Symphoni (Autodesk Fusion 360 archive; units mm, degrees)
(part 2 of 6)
extrude "Extrude4" new body sketch "Sketch25" profile of L1 L2 L4 C1 C2 L5 L6 L7 L8 L9 L10 L11 L12 L13 L14 L15 L16 C4 C5 along normal blind 3
extrude "Extrude5" new body sketch "Sketch24" profile of L1 L7 L10 L11 L12 L13 L14 L16 along normal blind 12 and against normal blind 9
combine "Combine1"
fillet "Fillet1" radius 1
offset_faces "OffsetFaces1" distance -0.1
sketch "Sketch26" plane through (0, 0, 13.9004) normal (0, 0, 1) x axis (-1, 0, 0)
  line L1 (-214.3877, -143.2359) -> (-214.3877, -209.1659)
  line L2 (-222.3877, -143.2359) -> (-214.3877, -143.2359)
  line L3 (-222.3877, -209.1659) -> (-222.3877, -143.2359)
  line L4 (-214.3877, -209.1659) -> (-222.3877, -209.1659)
  line L5 (-222.3877, -176.2009) -> (-214.3877, -176.2009)
  circle C1 centre (-218.3877, -156.5062) radius 2.1
  circle C2 centre (-218.3877, -195.8956) radius 2.1
  point P8 (-214.3877, -176.2009)
  point P9 (-222.3877, -176.2009)
  midpoint L1 P8
  midpoint L3 P9
  symmetric C1 C2 L5
  dimension "d225" diameter C1 = 4.2
  dimension "d226" diameter C2 = 4.2
extrude "Extrude6" cut sketch "Sketch26" profile of C1 C2 against normal blind 12
sketch "acrylic'" plane through (0, 0, 88.7) normal (0, 0, 1) x axis (-1, 0, 0)
  line L1 (-313.7625, -161.3779) -> (-313.7625, -215.1735)
  line L2 (-206.1516, -161.3779) -> (-313.7625, -161.3779)
  line L3 (-206.1516, -186.4735) -> (-206.1516, -161.3779)
  line L4 (-206.1515, -186.4735) -> (-206.1516, -186.4735)
  line L5 (-206.1515, -188.1735) -> (-206.1515, -186.4735)
  line L6 (-206.1516, -188.1735) -> (-206.1515, -188.1735)
  line L7 (-206.1516, -213.4735) -> (-206.1516, -188.1735)
  line L8 (-206.1515, -213.4735) -> (-206.1516, -213.4735)
  line L9 (-206.1515, -215.1735) -> (-206.1515, -213.4735)
  line L10 (-313.7625, -215.1735) -> (-206.1515, -215.1735)
  line L11 (-313.7625, -125.5942) -> (-313.7625, -152.5942)
  line L12 (-206.1516, -125.5942) -> (-313.7625, -125.5942)
  line L13 (-206.1516, -152.5942) -> (-206.1516, -125.5942)
  line L14 (-313.7625, -152.5942) -> (-206.1516, -152.5942)
  line L15 (-209.081, -225) -> (-311.081, -225)
  line L16 (-199.081, -5) -> (-199.081, -215)
  line L17 (-311.081, 5) -> (-209.081, 5)
  line L18 (-321.081, -215) -> (-321.081, -5)
  line L19 (-313.7625, -188.1735) -> (-206.1516, -188.1735)
  line L20 (-206.1515, -215.1735) -> (-313.7625, -215.1735)
  line L21 (-206.1515, -213.4735) -> (-206.1515, -215.1735)
  line L22 (-206.1516, -213.4735) -> (-206.1515, -213.4735)
  line L23 (-206.1516, -188.1735) -> (-206.1516, -213.4735)
  line L24 (-206.1516, -152.5942) -> (-313.7625, -152.5942)
  line L25 (-313.7625, -161.3779) -> (-206.1516, -161.3779)
  line L26 (-313.7625, -152.5942) -> (-313.7625, -125.5942)
  line L27 (-313.7625, -215.1735) -> (-313.7625, -188.1735)
  line L28 (-313.7625, -186.4735) -> (-313.7625, -161.3779)
  line L29 (-206.1516, -161.3779) -> (-206.1516, -186.4735)
  line L30 (-206.1516, -125.5942) -> (-206.1516, -152.5942)
  line L31 (-311.081, -225) -> (-209.081, -225)
  line L32 (-206.1516, -186.4735) -> (-313.7625, -186.4735)
  line L33 (-321.081, -5) -> (-321.081, -215)
  line L34 (-209.081, 5) -> (-311.081, 5)
  line L35 (-199.081, -215) -> (-199.081, -5)
  line L36 (-313.7625, -125.5942) -> (-206.1516, -125.5942)
  arc A1 centre (-311.081, -215) radius 10 clockwise from (-311.081, -225) to (-321.081, -215)
  arc A2 centre (-209.081, -215) radius 10 clockwise from (-199.081, -215) to (-209.081, -225)
  arc A3 centre (-209.081, -5) radius 10 clockwise from (-209.081, 5) to (-199.081, -5)
  arc A4 centre (-311.081, -5) radius 10 clockwise from (-321.081, -5) to (-311.081, 5)
  arc A5 centre (-311.081, -215) radius 10 clockwise from (-311.081, -225) to (-321.081, -215)
  arc A6 centre (-311.081, -5) radius 10 clockwise from (-321.081, -5) to (-311.081, 5)
  arc A7 centre (-209.081, -5) radius 10 clockwise from (-209.081, 5) to (-199.081, -5)
  arc A8 centre (-209.081, -215) radius 10 clockwise from (-199.081, -215) to (-209.081, -225)
position "Position16"
copy_paste "CopyPaste1"
component_from_bodies "Body->Comp14"
as_built_joint "As-built2"
as_built_joint "As-built3"
position "Position17"
sketch "Sketch29" plane through (0, 0, 85) normal (0, 0, 1) x axis (-1, 0, 0)
  line L1 (-207.0809, -138.3115) -> (-215.3243, -138.3115)
  line L2 (-207.0809, -205.1908) -> (-207.0809, -138.3115)
  line L3 (-318.7625, -205.1908) -> (-207.0809, -205.1908)
  line L4 (-318.7625, -138.3115) -> (-318.7625, -205.1908)
  line L5 (-315.3243, -138.3115) -> (-318.7625, -138.3115)
  line L6 (-315.3243, -25.6421) -> (-315.3243, -138.3115)
  line L7 (-215.3243, -25.6421) -> (-315.3243, -25.6421)
  line L8 (-215.3243, -138.3115) -> (-215.3243, -25.6421)
  line L9 (-330.9988, 0) -> (-19.0012, 0)
  line L10 (-330.9988, -252) -> (-330.9988, 0)
  line L11 (-19.0012, -252) -> (-330.9988, -252)
  line L12 (-19.0012, 0) -> (-19.0012, -252)
  circle C1 centre (-107.2113, -126.4161) radius 53.6774
  circle C2 centre (-107.2113, -126.4161) radius 54.6774
  dimension "d246" = 1
extrude "Extrude7" cut sketch "Sketch29" profile of C1 C2 against normal blind 20
component_insert "Component Insert11"
work_plane "WorkPlane13" AlongDistance -18
extrude "Extrude7" new body sketch "Sketch19" profile of L1 A1 L2 A2 L3 A3 L4 A4 A9 L9 A10 L10 A11 L11 A12 L12 C1 A13 A14 A15 A16 A17 A18 A19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 along normal blind 2
sketch "Sketch28" plane through (0, -20, 0) normal (0, -1, 0) x axis (1, 0, 0)
  line L1 (345, 75) -> (345, 10)
  line L2 (10, 80) -> (340, 80)
  line L3 (5, 10) -> (5, 75)
  line L4 (340, 5) -> (10, 5)
  line L5 (340, 5) -> (10, 5)
  line L6 (5, 10) -> (5, 75)
  line L7 (10, 80) -> (340, 80)
  line L8 (345, 75) -> (345, 10)
  line L9 (350, 75) -> (350, 10)
  line L10 (340, 0) -> (10, 0)
  line L11 (0, 10) -> (0, 75)
  line L12 (10, 85) -> (340, 85)
  arc A1 centre (340, 75) radius 5 clockwise from (340, 80) to (345, 75)
  arc A2 centre (10, 75) radius 5 clockwise from (5, 75) to (10, 80)
  arc A3 centre (10, 10) radius 5 clockwise from (10, 5) to (5, 10)
  arc A4 centre (340, 10) radius 5 clockwise from (345, 10) to (340, 5)
  arc A5 centre (340, 10) radius 5 clockwise from (345, 10) to (340, 5)
  arc A6 centre (10, 10) radius 5 clockwise from (10, 5) to (5, 10)
  arc A7 centre (10, 75) radius 5 clockwise from (5, 75) to (10, 80)
  arc A8 centre (340, 75) radius 5 clockwise from (340, 80) to (345, 75)
  arc A9 centre (340, 75) radius 10 clockwise from (340, 85) to (350, 75)
  arc A10 centre (340, 10) radius 10 clockwise from (350, 10) to (340, 0)
  arc A11 centre (10, 10) radius 10 clockwise from (10, 0) to (0, 10)
  arc A12 centre (10, 75) radius 10 clockwise from (0, 75) to (10, 85)
component_insert "Component Insert10"
position "Position15"
extrude "Extrude8" cut sketch "Sketch16" profile of L7 L8 L9 L10 against normal blind 3
extrude "Extrude9" cut sketch "Sketch17" profile of C1 against normal blind 20
sketch "Sketch18" plane through (0, -16, 0) normal (0, -1, 0) x axis (1, 0, 0)
  circle C1 centre (72.9825, 42.5) radius 27.5
extrude "Extrude10" cut sketch "Sketch18" against normal blind 20
joint "Assemble2" alignAngle 0 alignOffsetX 0 alignOffsetY 0 alignOffsetZ 0
work_plane "WorkPlane1" AlongDistance -18
work_plane "WorkPlane2" AlongDistance -18
work_plane "WorkPlane3" AlongDistance -18
work_plane "WorkPlane4" AlongDistance -18
work_plane "WorkPlane5" AlongDistance -18
work_plane "WorkPlane6" AlongDistance -18
work_plane "WorkPlane7" AlongDistance -18
work_plane "WorkPlane8" AlongDistance -18
work_plane "WorkPlane9" AlongDistance -18
work_plane "WorkPlane10" AlongDistance -18
work_plane "WorkPlane11" AlongDistance -18
copy_paste_bodies "CopyPasteBodies1"
split "Split1"
as_built_joint "As-built1"
sketch "Sketch4" plane through (0, 0, 85) normal (0, 0, 1) x axis (-1, 0, 0)
  line L1 (-207.0809, -138.3115) -> (-215.3243, -138.3115)
  line L2 (-207.0809, -205.1908) -> (-207.0809, -138.3115)
  line L3 (-318.7625, -205.1908) -> (-207.0809, -205.1908)
  line L4 (-318.7625, -138.3115) -> (-318.7625, -205.1908)
  line L5 (-315.3243, -138.3115) -> (-318.7625, -138.3115)
  line L6 (-315.3243, -25.6421) -> (-315.3243, -138.3115)
  line L7 (-215.3243, -25.6421) -> (-315.3243, -25.6421)
  line L8 (-215.3243, -138.3115) -> (-215.3243, -25.6421)
  line L9 (-330.9988, 0) -> (-19.0012, 0)
  line L10 (-330.9988, -216) -> (-330.9988, 0)
  line L11 (-19.0012, -216) -> (-330.9988, -216)
  line L12 (-19.0012, 0) -> (-19.0012, -216)
component_from_bodies "Body->Comp2"
component_from_bodies "Body->Comp3"
component_from_bodies "Body->Comp4"
component_from_bodies "Body->Comp5"
component_from_bodies "Body->Comp6"
component_from_bodies "Body->Comp7"
component_from_bodies "Body->Comp8"
component_from_bodies "Body->Comp9"
component_from_bodies "Body->Comp10"
component_from_bodies "Body->Comp11"
component_from_bodies "Body->Comp12"
component_from_bodies "Body->Comp13"
sketch "Sketch5" plane through (0, 0, 0) normal (0, 0, 1) x axis (1, 0, 0)
  line L1 (-620, 0) -> (-400, 0)
  line L2 (-620, 530) -> (-620, 0)
  line L3 (-400, 1000) -> (-620, 1000)
  line L4 (-400, 0) -> (-400, 1000)
  line L5 (-1600, 1000) -> (-400, 1000)
  line L6 (-1600, 530) -> (-1600, 1000)
  line L7 (-620, 530) -> (-1600, 530)
  line L8 (-400, 1000) -> (-400, 530)
  point P2 (-400, 0)
  point P3 (-620, 0)
  point P5 (-400, 1000)
  point P6 (-1600, 1000)
  horizontal L1
  vertical L2
  horizontal L3
  vertical L4
  horizontal L5
  vertical L6
  horizontal L7
  vertical L8
  dimension "d89" distance P2 P3 = 220
  dimension "d90" distance P2 P5 = 1000
  dimension "d91" distance P5 P6 = 1200
  dimension "d92" distance L1 L7 = 530
step "Arrange1" sketch "Sketch5" AngleFromX 0 Priority 500 AngleFromX 0 Priority 500 AngleFromX 0 Priority 500 AngleFromX 0 Priority 500 AngleFromX 0 Priority 500 AngleFromX 0 Priority 500 AngleFromX 0 Priority 500 AngleFromX 0 Priority 500 AngleFromX 0 Priority 500 AngleFromX 0 Priority 500 AngleFromX 0 Priority 500 AngleFromX 0 Priority 500 originOffsetX 0 originOffsetY 0 grainDirection 0 objectSpacing 18 frameWidth 20 placementClearance 0
component_insert "Component Insert6"
position "Position6"
sketch "Sketch6" plane through (0, 0, 0) normal (0, 0, 1) x axis (1, 0, 0)
  line L1 (-681.6057, 956.4633) -> (-681.6057, 944.4633)
  line L2 (-674.6057, 956.4633) -> (-681.6057, 956.4633)
  line L3 (-674.6057, 965.4645) -> (-674.6057, 956.4633)
  line L4 (-749.6057, 975.4645) -> (-684.6057, 975.4645)
  line L5 (-759.6057, 635.4645) -> (-759.6057, 965.4645)
  line L6 (-684.6057, 625.4645) -> (-749.6057, 625.4645)
  line L7 (-674.6057, 644.4657) -> (-674.6057, 635.4645)
  line L8 (-681.6057, 644.4657) -> (-674.6057, 644.4657)
  line L9 (-681.6057, 656.4657) -> (-681.6057, 644.4657)
  line L10 (-686.6057, 656.4657) -> (-681.6057, 656.4657)
  line L11 (-686.6057, 639.6645) -> (-686.6057, 656.4657)
  line L12 (-742.6057, 637.4645) -> (-688.8057, 637.4645)
  line L13 (-747.6057, 958.4645) -> (-747.6057, 642.4645)
  line L14 (-688.6057, 963.4645) -> (-742.6057, 963.4645)
  line L15 (-686.6057, 944.4633) -> (-686.6057, 961.4645)
  line L16 (-681.6057, 944.4633) -> (-686.6057, 944.4633)
  line L17 (-789.6057, 593.4633) -> (-789.6057, 909.4633)
  line L18 (-848.6057, 588.4633) -> (-794.6057, 588.4633)
  line L19 (-850.6057, 607.4645) -> (-850.6057, 590.4633)
  line L20 (-855.6057, 607.4645) -> (-850.6057, 607.4645)
  line L21 (-855.6057, 595.4645) -> (-855.6057, 607.4645)
  line L22 (-862.6057, 595.4645) -> (-855.6057, 595.4645)
  line L23 (-862.6057, 586.4633) -> (-862.6057, 595.4645)
  line L24 (-787.6057, 576.4633) -> (-852.6057, 576.4633)
  line L25 (-777.6057, 916.4633) -> (-777.6057, 586.4633)
  line L26 (-852.6057, 926.4633) -> (-787.6057, 926.4633)
  line L27 (-862.6057, 907.4621) -> (-862.6057, 916.4633)
  line L28 (-855.6057, 907.4621) -> (-862.6057, 907.4621)
  line L29 (-855.6057, 895.4621) -> (-855.6057, 907.4621)
  line L30 (-850.6057, 895.4621) -> (-855.6057, 895.4621)
  line L31 (-850.6057, 912.2633) -> (-850.6057, 895.4621)
  line L32 (-794.6057, 914.4633) -> (-848.4057, 914.4633)
  line L33 (-816.07, 944.4633) -> (-821.07, 944.4633)
  line L34 (-816.07, 956.4633) -> (-816.07, 944.4633)
  line L35 (-809.07, 956.4633) -> (-816.07, 956.4633)
  line L36 (-809.07, 965.4645) -> (-809.07, 956.4633)
  line L37 (-884.07, 975.4645) -> (-819.07, 975.4645)
  line L38 (-894.07, 635.4645) -> (-894.07, 965.4645)
  line L39 (-819.07, 625.4645) -> (-884.07, 625.4645)
  line L40 (-809.07, 644.4657) -> (-809.07, 635.4645)
  line L41 (-816.07, 644.4657) -> (-809.07, 644.4657)
  line L42 (-816.07, 656.4657) -> (-816.07, 644.4657)
  line L43 (-821.07, 656.4657) -> (-816.07, 656.4657)
  line L44 (-821.07, 639.6645) -> (-821.07, 656.4657)
  line L45 (-877.07, 637.4645) -> (-823.27, 637.4645)
  line L46 (-882.07, 958.4645) -> (-882.07, 642.4645)
  line L47 (-823.07, 963.4645) -> (-877.07, 963.4645)
  line L48 (-821.07, 944.4633) -> (-821.07, 961.4645)
  line L49 (-987.07, 926.4633) -> (-922.07, 926.4633)
  line L50 (-997.07, 907.4621) -> (-997.07, 916.4633)
  line L51 (-990.07, 907.4621) -> (-997.07, 907.4621)
  line L52 (-990.07, 895.4621) -> (-990.07, 907.4621)
  line L53 (-985.07, 895.4621) -> (-990.07, 895.4621)
  line L54 (-985.07, 912.2633) -> (-985.07, 895.4621)
  line L55 (-929.07, 914.4633) -> (-982.87, 914.4633)
  line L56 (-924.07, 593.4633) -> (-924.07, 909.4633)
  line L57 (-983.07, 588.4633) -> (-929.07, 588.4633)
  line L58 (-985.07, 607.4645) -> (-985.07, 590.4633)
  line L59 (-990.07, 607.4645) -> (-985.07, 607.4645)
  line L60 (-990.07, 595.4645) -> (-990.07, 607.4645)
  line L61 (-997.07, 595.4645) -> (-990.07, 595.4645)
  line L62 (-997.07, 586.4633) -> (-997.07, 595.4645)
  line L63 (-922.07, 576.4633) -> (-987.07, 576.4633)
  line L64 (-912.07, 916.4633) -> (-912.07, 586.4633)
  line L65 (-957.5344, 963.4645) -> (-1011.5344, 963.4645)
  line L66 (-955.5344, 944.4633) -> (-955.5344, 961.4645)
  line L67 (-950.5344, 944.4633) -> (-955.5344, 944.4633)
  line L68 (-950.5344, 956.4633) -> (-950.5344, 944.4633)
  line L69 (-943.5344, 956.4633) -> (-950.5344, 956.4633)
  line L70 (-943.5344, 965.4645) -> (-943.5344, 956.4633)
  line L71 (-1018.5344, 975.4645) -> (-953.5344, 975.4645)
  line L72 (-1028.5344, 635.4645) -> (-1028.5344, 965.4645)
  line L73 (-953.5344, 625.4645) -> (-1018.5344, 625.4645)
  line L74 (-943.5344, 644.4657) -> (-943.5344, 635.4645)
  line L75 (-950.5344, 644.4657) -> (-943.5344, 644.4657)
  line L76 (-950.5344, 656.4657) -> (-950.5344, 644.4657)
  line L77 (-955.5344, 656.4657) -> (-950.5344, 656.4657)
  line L78 (-955.5344, 639.6645) -> (-955.5344, 656.4657)
  line L79 (-1011.5344, 637.4645) -> (-957.7344, 637.4645)
  line L80 (-1016.5344, 958.4645) -> (-1016.5344, 642.4645)
  line L81 (-1089.9988, 944.4633) -> (-1089.9988, 961.4645)
  line L82 (-1084.9988, 944.4633) -> (-1089.9988, 944.4633)
  line L83 (-1084.9988, 956.4633) -> (-1084.9988, 944.4633)
  line L84 (-1077.9988, 956.4633) -> (-1084.9988, 956.4633)
  line L85 (-1077.9988, 965.4645) -> (-1077.9988, 956.4633)
  line L86 (-1152.9988, 975.4645) -> (-1087.9988, 975.4645)
  line L87 (-1162.9988, 635.4645) -> (-1162.9988, 965.4645)
  line L88 (-1087.9988, 625.4645) -> (-1152.9988, 625.4645)
  line L89 (-1077.9988, 644.4657) -> (-1077.9988, 635.4645)
  line L90 (-1084.9988, 644.4657) -> (-1077.9988, 644.4657)
  line L91 (-1084.9988, 656.4657) -> (-1084.9988, 644.4657)
  line L92 (-1089.9988, 656.4657) -> (-1084.9988, 656.4657)
  line L93 (-1089.9988, 639.6645) -> (-1089.9988, 656.4657)
  line L94 (-1145.9988, 637.4645) -> (-1092.1988, 637.4645)
  line L95 (-1150.9988, 958.4645) -> (-1150.9988, 642.4645)
  line L96 (-1091.9988, 963.4645) -> (-1145.9988, 963.4645)
  line L97 (-1563, 871) -> (-1247, 871)
  line L98 (-1568, 930) -> (-1568, 876)
  line L99 (-1548.9988, 932) -> (-1566, 932)
  line L100 (-1548.9988, 937) -> (-1548.9988, 932)
  line L101 (-1560.9988, 937) -> (-1548.9988, 937)
  line L102 (-1560.9988, 944) -> (-1560.9988, 937)
  line L103 (-1570, 944) -> (-1560.9988, 944)
  line L104 (-1580, 869) -> (-1580, 934)
  line L105 (-1240, 859) -> (-1570, 859)
  line L106 (-1230, 934) -> (-1230, 869)
  line L107 (-1249.0012, 944) -> (-1240, 944)
  line L108 (-1249.0012, 937) -> (-1249.0012, 944)
  line L109 (-1261.0012, 937) -> (-1249.0012, 937)
  line L110 (-1261.0012, 932) -> (-1261.0012, 937)
  line L111 (-1244.2, 932) -> (-1261.0012, 932)
  line L112 (-1242, 876) -> (-1242, 929.8)
  line L113 (-1516.7988, 902.4645) -> (-1499.9976, 902.4645)
  line L114 (-1518.9988, 958.4645) -> (-1518.9988, 904.6645)
  line L115 (-1197.9988, 963.4645) -> (-1513.9988, 963.4645)
  line L116 (-1192.9988, 904.4645) -> (-1192.9988, 958.4645)
  line L117 (-1212, 902.4645) -> (-1194.9988, 902.4645)
  line L118 (-1212, 897.4645) -> (-1212, 902.4645)
  line L119 (-1200, 897.4645) -> (-1212, 897.4645)
  line L120 (-1200, 890.4645) -> (-1200, 897.4645)
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position "Position7"
sketch "Sketch7" plane through (0, 228, 0) normal (0, 1, 0) x axis (-1, 0, 0)
  line L1 (-132.5, 60) -> (-217.5, 60)
  line L2 (-127.5, 30) -> (-127.5, 55)
  line L3 (-217.5, 25) -> (-132.5, 25)
  line L4 (-222.5, 55) -> (-222.5, 30)
  line L5 (-340, 85) -> (-10, 85)
  line L6 (-350, 10) -> (-350, 75)
  line L7 (-10, 0) -> (-340, 0)
  line L8 (0, 75) -> (0, 10)
  line L9 (0, 42.5) -> (-350, 42.5)
  line L10 (-175, 0) -> (-175, 85)
  circle C1 centre (-175, 6.9916) radius 2
  circle C2 centre (-340, 6.9916) radius 2
  circle C3 centre (-9.989, 78) radius 2
  circle C4 centre (-175, 79) radius 2
  circle C5 centre (-340, 78) radius 2
  circle C6 centre (-10, 7.35) radius 2
  arc A1 centre (-217.5, 55) radius 5 clockwise from (-222.5, 55) to (-217.5, 60)
  arc A2 centre (-132.5, 55) radius 5 clockwise from (-132.5, 60) to (-127.5, 55)
  arc A3 centre (-132.5, 30) radius 5 clockwise from (-127.5, 30) to (-132.5, 25)
  arc A4 centre (-217.5, 30) radius 5 clockwise from (-217.5, 25) to (-222.5, 30)
  arc A5 centre (-340, 75) radius 10 clockwise from (-350, 75) to (-340, 85)
  arc A6 centre (-340, 10) radius 10 clockwise from (-340, 0) to (-350, 10)
  arc A7 centre (-10, 10) radius 10 clockwise from (0, 10) to (-10, 0)
  arc A8 centre (-10, 75) radius 10 clockwise from (-10, 85) to (0, 75)
  point P32 (-350, 42.5)
  point P33 (0, 42.5)
  point P34 (-175, 85)
  point P35 (-175, 0)
  point P36 (-175, 42.5)
  midpoint L6 P32
  midpoint L8 P33
  midpoint L5 P34
  midpoint L7 P35
  midpoint L9 P36
position "Position8"
sketch "Sketch8" plane through (0, 228, 0) normal (0, 1, 0) x axis (-1, 0, 0)
  line L1 (-132.5, 60) -> (-217.5, 60)
  line L2 (-127.5, 30) -> (-127.5, 55)
  line L3 (-217.5, 25) -> (-132.5, 25)
  line L4 (-222.5, 55) -> (-222.5, 30)
  line L5 (-340, 85) -> (-10, 85)
  line L6 (-350, 10) -> (-350, 75)
  line L7 (-10, 0) -> (-340, 0)
  line L8 (0, 75) -> (0, 10)
  line L9 (-340, 85) -> (-10, 85)
  line L10 (-350, 10) -> (-350, 75)
  line L11 (-10, 0) -> (-340, 0)
  line L12 (0, 75) -> (0, 10)
  line L13 (-132.5, 60) -> (-217.5, 60)
  line L14 (-127.5, 30) -> (-127.5, 55)
  line L15 (-217.5, 25) -> (-132.5, 25)
  line L16 (-222.5, 55) -> (-222.5, 30)
  circle C1 centre (-175, 6.9916) radius 2
  circle C2 centre (-340, 6.9916) radius 2
  circle C3 centre (-9.989, 78) radius 2
  circle C4 centre (-175, 79) radius 2
  circle C5 centre (-340, 78) radius 2
  circle C6 centre (-10, 7.35) radius 2
  arc A1 centre (-217.5, 55) radius 5 clockwise from (-222.5, 55) to (-217.5, 60)
  arc A2 centre (-132.5, 55) radius 5 clockwise from (-132.5, 60) to (-127.5, 55)
  arc A3 centre (-132.5, 30) radius 5 clockwise from (-127.5, 30) to (-132.5, 25)
  arc A4 centre (-217.5, 30) radius 5 clockwise from (-217.5, 25) to (-222.5, 30)
  arc A5 centre (-340, 75) radius 10 clockwise from (-350, 75) to (-340, 85)
  arc A6 centre (-340, 10) radius 10 clockwise from (-340, 0) to (-350, 10)
  arc A7 centre (-10, 10) radius 10 clockwise from (0, 10) to (-10, 0)
  arc A8 centre (-10, 75) radius 10 clockwise from (-10, 85) to (0, 75)
  arc A9 centre (-340, 75) radius 10 clockwise from (-350, 75) to (-340, 85)
  arc A10 centre (-340, 10) radius 10 clockwise from (-340, 0) to (-350, 10)
  arc A11 centre (-10, 10) radius 10 clockwise from (0, 10) to (-10, 0)
  arc A12 centre (-10, 75) radius 10 clockwise from (-10, 85) to (0, 75)
  arc A13 centre (-132.5, 55) radius 5 clockwise from (-132.5, 60) to (-127.5, 55)
  arc A14 centre (-132.5, 30) radius 5 clockwise from (-127.5, 30) to (-132.5, 25)
  arc A15 centre (-217.5, 30) radius 5 clockwise from (-217.5, 25) to (-222.5, 30)
  arc A16 centre (-217.5, 55) radius 5 clockwise from (-222.5, 55) to (-217.5, 60)
sketch "Sketch9" plane through (0, 0, 0) normal (0, 1, 0) x axis (1, 0, 0)
  line L1 (-50, 0) -> (-50, -250)
  line L2 (436.214, 0) -> (-50, 0)
  line L3 (510, 0) -> (-50, 0)
  line L4 (510, -250) -> (510, 0)
  line L5 (-50, -250) -> (280, -250)
  line L6 (-50, 0) -> (-50, -250)
  line L7 (280, 0) -> (510, 0)
  line L8 (280, -390) -> (280, -250)
  line L9 (510, 0) -> (510, -390)
  line L10 (510, -547.191) -> (280, -390)
  line L11 (510, -390) -> (510, -547.191)
  point P2 (-50, 0)
  point P4 (510, 0)
  point P6 (-50, -250)
  point P7 (280, 0)
  point P9 (510, -390)
  vertical L1
  horizontal L2
  horizontal L3
  vertical L4
  horizontal L5
  vertical L6
  horizontal L7
  vertical L8
  vertical L9
  vertical L11
  dimension "d124" distance P2 P4 = 560
  dimension "d125" distance P2 P6 = 250
  dimension "d126" distance P4 P7 = 230
  dimension "d127" distance P4 P9 = 390
step "Arrange2" sketch "Sketch9" AngleFromX 0 Priority 500 AngleFromX 0 Priority 500 AngleFromX 0 Priority 500 originOffsetX 0 originOffsetY 0 grainDirection 0 objectSpacing 18 frameWidth 20 placementClearance 0
sketch "Sketch10" plane through (0, 0, 0) normal (0, 1, 0) x axis (1, 0, 0)
  line L1 (-20, -230) -> (310, -230)
  line L2 (310, -145) -> (-20, -145)
  line L3 (-30, -155) -> (-30, -220)
  line L4 (320, -220) -> (320, -155)
  line L5 (192.5, -175) -> (192.5, -200)
  line L6 (187.5, -205) -> (102.5, -205)
  line L7 (97.5, -200) -> (97.5, -175)
  line L8 (102.5, -170) -> (187.5, -170)
  line L9 (310, -127) -> (-20, -127)
  line L10 (-30, -117) -> (-30, -52)
  line L11 (-20, -42) -> (-10.9988, -42)
  line L12 (-10.9988, -42) -> (-10.9988, -49)
  line L13 (-10.9988, -49) -> (1.0012, -49)
  line L14 (1.0012, -49) -> (1.0012, -54)
  line L15 (1.0012, -54) -> (-15.8, -54)
  line L16 (-18, -56.2) -> (-18, -110)
  line L17 (-13, -115) -> (303, -115)
  line L18 (308, -110) -> (308, -56)
  line L19 (306, -54) -> (288.9988, -54)
  line L20 (288.9988, -54) -> (288.9988, -49)
  line L21 (288.9988, -49) -> (300.9988, -49)
  line L22 (300.9988, -49) -> (300.9988, -42)
  line L23 (300.9988, -42) -> (310, -42)
  line L24 (320, -52) -> (320, -117)
  line L25 (413, -392) -> (348, -392)
  line L26 (423, -372.9988) -> (423, -382)
  line L27 (416, -372.9988) -> (423, -372.9988)
  line L28 (416, -360.9988) -> (416, -372.9988)
  line L29 (411, -360.9988) -> (416, -360.9988)
  line L30 (411, -378) -> (411, -360.9988)
  line L31 (355, -380) -> (409, -380)
  line L32 (350, -59) -> (350, -375)
  line L33 (408.8, -54) -> (355, -54)
  line L34 (411, -73.0012) -> (411, -56.2)
  line L35 (416, -73.0012) -> (411, -73.0012)
  line L36 (416, -61.0012) -> (416, -73.0012)
  line L37 (423, -61.0012) -> (416, -61.0012)
  line L38 (423, -52) -> (423, -61.0012)
  line L39 (348, -42) -> (413, -42)
  line L40 (338, -382) -> (338, -52)
  arc A1 centre (-20, -155) radius 10 clockwise from (-30, -155) to (-20, -145)
  arc A2 centre (-20, -220) radius 10 clockwise from (-20, -230) to (-30, -220)
  arc A3 centre (310, -155) radius 10 clockwise from (310, -145) to (320, -155)
  arc A4 centre (310, -220) radius 10 clockwise from (320, -220) to (310, -230)
  arc A5 centre (102.5, -175) radius 5 clockwise from (97.5, -175) to (102.5, -170)
  arc A6 centre (102.5, -200) radius 5 clockwise from (102.5, -205) to (97.5, -200)
  arc A7 centre (187.5, -175) radius 5 clockwise from (187.5, -170) to (192.5, -175)
  arc A8 centre (187.5, -200) radius 5 clockwise from (192.5, -200) to (187.5, -205)
  arc A9 centre (-20, -117) radius 10 clockwise from (-20, -127) to (-30, -117)
  arc A10 centre (-20, -52) radius 10 clockwise from (-30, -52) to (-20, -42)
  arc A11 centre (-15.8, -56.2) radius 2.2 clockwise from (-18, -56.2) to (-15.8, -54)
  arc A12 centre (-13, -110) radius 5 clockwise from (-13, -115) to (-18, -110)
  arc A13 centre (303, -110) radius 5 clockwise from (308, -110) to (303, -115)
  arc A14 centre (306, -56) radius 2 clockwise from (306, -54) to (308, -56)
  arc A15 centre (310, -52) radius 10 clockwise from (310, -42) to (320, -52)
  arc A16 centre (310, -117) radius 10 clockwise from (320, -117) to (310, -127)
  arc A17 centre (348, -382) radius 10 clockwise from (348, -392) to (338, -382)
  arc A18 centre (413, -382) radius 10 clockwise from (423, -382) to (413, -392)
  arc A19 centre (409, -378) radius 2 clockwise from (411, -378) to (409, -380)
  arc A20 centre (355, -375) radius 5 clockwise from (355, -380) to (350, -375)
  arc A21 centre (355, -59) radius 5 clockwise from (350, -59) to (355, -54)
  arc A22 centre (408.8, -56.2) radius 2.2 clockwise from (408.8, -54) to (411, -56.2)
  arc A23 centre (413, -52) radius 10 clockwise from (413, -42) to (423, -52)
  arc A24 centre (348, -52) radius 10 clockwise from (338, -52) to (348, -42)
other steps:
base_feature "Base Feature1"
base_feature "Base Feature1" sketch "Sketch2"
extrude "Extrude1" cut sketch "Sketch2" profile of C1 C2 C3 C4 C5 C6 against normal blind 5 and along normal blind 15
base_feature "Base Feature1" bodies "Front"
extrude "Extrude3" cut sketch "Sketch3" profile of L5 L6 L7 L8 against normal blind 25
extrude "Extrude4" cut sketch "Sketch2" profile of C1 C2 C3 C4 C5 C6 against normal blind 5 and along normal blind 15
offset_faces "OffsetFaces1" distance 36
extrude "Extrude14" cut sketch "Sketch17" profile of L15 L16 L17 L22 against normal blind 6.5
create_component "CreateComponent1"
create_component "CreateComponent1"
create_component "CreateComponent2"
create_component "CreateComponent4" sketch "Sketch2"
place_component sketch "Sketch2"
remove_body "RemoveBody1"
base_feature "Base Feature1"
create_component "CreateComponent5"
base_feature "Base Feature1"
remove_body "RemoveBody2"
create_component "CreateComponent6"
base_feature "Base Feature1"
remove_body "RemoveBody3"
create_component "CreateComponent7"
base_feature "Base Feature1"
remove_body "RemoveBody4"
create_component "CreateComponent8"
base_feature "Base Feature1"
remove_body "RemoveBody5"
create_component "CreateComponent9"
base_feature "Base Feature1"
remove_body "RemoveBody6"
create_component "CreateComponent10"
base_feature "Base Feature1"
remove_body "RemoveBody7"
create_component "CreateComponent11"
base_feature "Base Feature1"
remove_body "RemoveBody8"
create_component "CreateComponent12"
base_feature "Base Feature1"
remove_body "RemoveBody9"
create_component "CreateComponent13"
base_feature "Base Feature1"
remove_body "RemoveBody10"
create_component "CreateComponent14"
base_feature "Base Feature1"
remove_body "RemoveBody11"
create_component "CreateComponent15"
base_feature "Base Feature1"
remove_body "RemoveBody12"
create_component "CreateComponent16"
base_feature "Base Feature1"
remove_body "RemoveBody13"
create_component "CreateComponent17"
create_component "CreateComponent1"
create_component "CreateComponent18"
create_component "CreateComponent1"
create_component "CreateComponent19" sketch "Sketch13"
joint_origin "JointOrigin1"
create_component "CreateComponent2"
remove_body "RemoveBody1"
joint_origin "JointOrigin10"
create_component "CreateComponent20"
create_component "CreateComponent21"
remove_body "RemoveBody14"
named bodies: "Front"

design "PCM5102_Modul_ksu_detail"
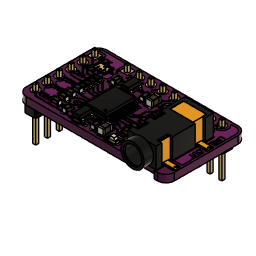
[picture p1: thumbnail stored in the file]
description: FreeCAD Model
part number: PCM5102_Modul
description: Part Number
part number: C13_C_0603_1608Metric_fe494fe29558
part number: U3_SOT_23_5_215b9efe0f9c
part number: U2_TSSOP_20_44x65mm_P065mm_d0068de2549f
part number: R7_R_0603_1608Metric_fcd2d6c932f5
part number: C2_C_0805_2012Metric_0ac201e7e1f9
part number: J3_PJ-327A_7183a15533ae
part number: D1_LED_0603_1608Metric_b5c2f6ca02fa
part number: Top_e102
part number: J2_PinHeader_1x09_P254mm_Vertical_94b9bb8abd76
base_feature "Base Feature1"
base_feature "Base Feature1"
base_feature "Base Feature1"
base_feature "Base Feature1"
base_feature "Base Feature1"
base_feature "Base Feature1"
base_feature "Base Feature1"
base_feature "Base Feature1"
base_feature "Base Feature1"
base_feature "Base Feature1"
base_feature "Base Feature1"
base_feature "Base Feature1"
base_feature "Base Feature1"
base_feature "Base Feature1"
base_feature "Base Feature1"
base_feature "Base Feature1"
base_feature "Base Feature1"
base_feature "Base Feature1"
sketch "Sketch1" plane through (0, 0, 0) normal (0, 0, 1) x axis (1, 0, 0)
  line L1 (1.8, -17.3) -> (23.58, -17.3)
  line L2 (0, -1.8) -> (0, -15.5)
  line L3 (23.58, -17.3) -> (23.93, -16.3)
  line L4 (23.93, -16.3) -> (28.93, -16.3)
  line L5 (28.93, -16.3) -> (29.28, -17.3)
  line L6 (29.28, -17.3) -> (30, -17.3)
  line L7 (31.8, -15.5) -> (31.8, -1.8)
  line L8 (30, 0) -> (1.8, 0)
  circle C1 centre (28.22, -1.7) radius 0.4999
  circle C2 centre (25.68, -1.7) radius 0.4999
  circle C3 centre (23.14, -1.7) radius 0.5
  circle C4 centre (20.6, -1.7) radius 0.5
  circle C5 centre (18.06, -1.7) radius 0.5
  circle C6 centre (15.52, -1.7) radius 0.4999
  circle C7 centre (12.98, -1.7) radius 0.5
  circle C8 centre (7.9, -1.7) radius 0.5
  circle C9 centre (1.55, -2.335) radius 0.5
  circle C10 centre (1.55, -4.875) radius 0.4999
  circle C11 centre (1.55, -7.415) radius 0.5
  circle C12 centre (1.55, -9.955) radius 0.5
  circle C13 centre (1.55, -12.495) radius 0.5
  circle C14 centre (1.55, -15.035) radius 0.5
  arc A1 centre (1.8, -15.5) radius 1.8 clockwise from (1.8, -17.3) to (0, -15.5)
  arc A2 centre (30, -15.5) radius 1.8 clockwise from (31.8, -15.5) to (30, -17.3)
  arc A3 centre (30, -1.8) radius 1.8 clockwise from (30, 0) to (31.8, -1.8)
  arc A4 centre (1.8, -1.8) radius 1.8 clockwise from (0, -1.8) to (1.8, 0)
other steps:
create_component "CreateComponent1"
create_component "CreateComponent1"
create_component "CreateComponent1"
create_component "CreateComponent2"
create_component "CreateComponent3"
create_component "CreateComponent4"
create_component "CreateComponent5"
create_component "CreateComponent6"
create_component "CreateComponent7"
create_component "CreateComponent2"
create_component "CreateComponent1"
create_component "CreateComponent2"
create_component "CreateComponent2"
create_component "CreateComponent1"
create_component "CreateComponent2"
create_component "CreateComponent3"
create_component "CreateComponent4"
create_component "CreateComponent5"
create_component "CreateComponent6"
create_component "CreateComponent7"
create_component "CreateComponent8"
create_component "CreateComponent9"

design "N20 DC MOTOR"
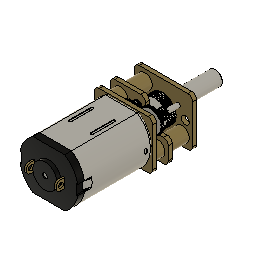
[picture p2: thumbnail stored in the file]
description: STEP AP214
part number: N20 DC MOTOR
base_feature "Base Feature"

design "New_Playback"
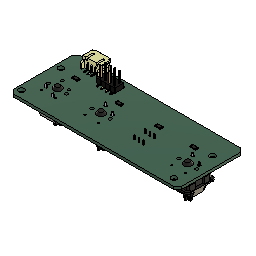
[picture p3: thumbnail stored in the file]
description: KiCad electronic assembly
part number: Playback_Controls 1
description: Part Number
part number: Ceramic
part number: Contacts
part number: Contacts (Mirror #1)
part number: Overcoat
part number: Resistor-1206
part number: PinHeader_2x04_P2.54mm_Vertical_SMD
part number: S3B-PH-SM4-TB--3DModel-STEP-269445
part number: MX1A-11NN
part number: SW_Btn_XLX
base_feature "Base Feature1"
base_feature "Base Feature1"
base_feature "Base Feature1"
base_feature "Base Feature1"
base_feature "Base Feature1"
base_feature "Base Feature1"
base_feature "Base Feature1"
base_feature "Base Feature1"
base_feature "Base Feature1"
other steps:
create_component "CreateComponent1"
create_component "CreateComponent1"
create_component "CreateComponent2"
create_component "CreateComponent3"
create_component "CreateComponent4"
create_component "CreateComponent2"
create_component "CreateComponent3"
create_component "CreateComponent4"
create_component "CreateComponent5"
create_component "CreateComponent6"

design "Laser Panel" references "LCD Display Mount", "Playback_Controls", "New_Playback", "XH-M577", "Playback_Controls_larger"
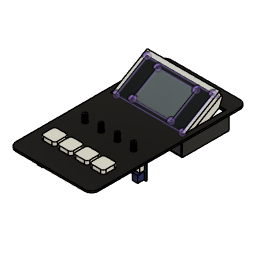
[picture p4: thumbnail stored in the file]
part number: Cherry MX Keycap
component_insert "Component Insert1"
position "Position1"
component_insert "Component Insert2"
component_insert "Component Insert3"
sketch "Sketch2" plane through (0, 0, 16.7) normal (0, 0, 1) x axis (-1, 0, 0)
  line L1 (36.7, 1.8) -> (36.7, 2.4)
  line L2 (38.05, 1.8) -> (36.7, 1.8)
  line L3 (38.05, 4.5) -> (38.05, 1.8)
  line L4 (40.45, 5.7) -> (39.1552, 5.7)
  line L5 (40.45, 12.8) -> (40.45, 5.7)
  line L6 (33.35, 12.8) -> (40.45, 12.8)
  line L7 (33.35, 11.5) -> (33.35, 12.8)
  line L8 (30.95, 10.2) -> (32.0499, 10.2)
  line L9 (30.95, 1.8) -> (30.95, 10.2)
  line L10 (34.7, 1.8) -> (30.95, 1.8)
  line L11 (34.7, 2.4) -> (34.7, 1.8)
  line L12 (36.7, 2.4) -> (34.7, 2.4)
  curve K1 (37.544, 5.3651) -> (37.1495, 11.1005)
  curve K2 (34.2541, 11.0973) -> (33.9191, 5.3212)
  line L13 (48.35, 0) -> (-48.35, 0)
  line L14 (48.35, 1.6) -> (48.35, 0)
  line L15 (-48.35, 1.6) -> (48.35, 1.6)
  line L16 (-48.35, 0) -> (-48.35, 1.6)
  line L17 (50, 97.6631) -> (-50, 97.6631)
  line L18 (50, -97.6631) -> (50, 97.6631)
  line L19 (-50, -97.6631) -> (50, -97.6631)
  line L20 (-50, 97.6631) -> (-50, -97.6631)
  line L21 (50, -97.6631) -> (-50, 97.6631)
  line L22 (-50, -97.6631) -> (50, 97.6631)
  line L23 (55, 115) -> (-55, 115)
  line L24 (55, -115) -> (55, 115)
  line L25 (-55, -115) -> (55, -115)
  line L26 (-55, 115) -> (-55, -115)
  line L27 (55, -115) -> (-55, 115)
  line L28 (-55, -115) -> (55, 115)
  line L29 (12.7, 1.8) -> (12.7, 2.4)
  line L30 (14.05, 1.8) -> (12.7, 1.8)
  line L31 (14.05, 4.5) -> (14.05, 1.8)
  line L32 (16.45, 5.7) -> (15.1552, 5.7)
  line L33 (16.45, 12.8) -> (16.45, 5.7)
  line L34 (9.35, 12.8) -> (16.45, 12.8)
  line L35 (9.35, 11.5) -> (9.35, 12.8)
  line L36 (6.95, 10.2) -> (8.0499, 10.2)
  line L37 (6.95, 1.8) -> (6.95, 10.2)
  line L38 (10.7, 1.8) -> (6.95, 1.8)
  line L39 (10.7, 2.4) -> (10.7, 1.8)
  line L40 (12.7, 2.4) -> (10.7, 2.4)
  curve K3 (13.544, 5.3651) -> (13.1495, 11.1005)
  curve K4 (10.2541, 11.0973) -> (9.9191, 5.3212)
  line L41 (-11.3, 1.8) -> (-11.3, 2.4)
  line L42 (-9.95, 1.8) -> (-11.3, 1.8)
  line L43 (-9.95, 4.5) -> (-9.95, 1.8)
  line L44 (-7.55, 5.7) -> (-8.8448, 5.7)
  line L45 (-7.55, 12.8) -> (-7.55, 5.7)
  line L46 (-14.65, 12.8) -> (-7.55, 12.8)
  line L47 (-14.65, 11.5) -> (-14.65, 12.8)
  line L48 (-17.05, 10.2) -> (-15.9501, 10.2)
  line L49 (-17.05, 1.8) -> (-17.05, 10.2)
  line L50 (-13.3, 1.8) -> (-17.05, 1.8)
  line L51 (-13.3, 2.4) -> (-13.3, 1.8)
  line L52 (-11.3, 2.4) -> (-13.3, 2.4)
  curve K5 (-10.456, 5.3651) -> (-10.8505, 11.1005)
  curve K6 (-13.7459, 11.0973) -> (-14.0809, 5.3212)
  line L53 (-35.3, 1.8) -> (-35.3, 2.4)
  line L54 (-33.95, 1.8) -> (-35.3, 1.8)
  line L55 (-33.95, 4.5) -> (-33.95, 1.8)
  line L56 (-31.55, 5.7) -> (-32.8448, 5.7)
  line L57 (-31.55, 12.8) -> (-31.55, 5.7)
  line L58 (-38.65, 12.8) -> (-31.55, 12.8)
  line L59 (-38.65, 11.5) -> (-38.65, 12.8)
  line L60 (-41.05, 10.2) -> (-39.9501, 10.2)
  line L61 (-41.05, 1.8) -> (-41.05, 10.2)
  line L62 (-37.3, 1.8) -> (-41.05, 1.8)
  line L63 (-37.3, 2.4) -> (-37.3, 1.8)
  line L64 (-35.3, 2.4) -> (-37.3, 2.4)
  curve K7 (-34.456, 5.3651) -> (-34.8505, 11.1005)
  curve K8 (-37.7459, 11.0973) -> (-38.0809, 5.3212)
  arc A1 centre (39.2541, 4.5) radius 1.2041 clockwise from (38.05, 4.5) to (39.1552, 5.7)
  arc A2 centre (32.0499, 11.5001) radius 1.3001 clockwise from (33.35, 11.5) to (32.0499, 10.2)
  arc A3 centre (35.7, 7.95) radius 3.4635 clockwise from (34.2541, 11.0973) to (37.1467, 11.0969)
  arc A4 centre (35.7, 7.95) radius 3.1752 clockwise from (37.544, 5.3651) to (33.9191, 5.3212)
  arc A5 centre (15.2541, 4.5) radius 1.2041 clockwise from (14.05, 4.5) to (15.1552, 5.7)
  arc A6 centre (8.0499, 11.5001) radius 1.3001 clockwise from (9.35, 11.5) to (8.0499, 10.2)
  arc A7 centre (11.7, 7.95) radius 3.4635 clockwise from (10.2541, 11.0973) to (13.1467, 11.0969)
  arc A8 centre (11.7, 7.95) radius 3.1752 clockwise from (13.544, 5.3651) to (9.9191, 5.3212)
  arc A9 centre (-8.7459, 4.5) radius 1.2041 clockwise from (-9.95, 4.5) to (-8.8448, 5.7)
  arc A10 centre (-15.9501, 11.5001) radius 1.3001 clockwise from (-14.65, 11.5) to (-15.9501, 10.2)
  arc A11 centre (-12.3, 7.95) radius 3.4635 clockwise from (-13.7459, 11.0973) to (-10.8533, 11.0969)
  arc A12 centre (-12.3, 7.95) radius 3.1753 clockwise from (-10.456, 5.3651) to (-14.0809, 5.3212)
  arc A13 centre (-32.7459, 4.5) radius 1.2041 clockwise from (-33.95, 4.5) to (-32.8448, 5.7)
  arc A14 centre (-39.9501, 11.5001) radius 1.3001 clockwise from (-38.65, 11.5) to (-39.9501, 10.2)
  arc A15 centre (-36.3, 7.95) radius 3.4635 clockwise from (-37.7459, 11.0973) to (-34.8533, 11.0969)
  arc A16 centre (-36.3, 7.95) radius 3.1752 clockwise from (-34.456, 5.3651) to (-38.0809, 5.3212)
  circle C1 centre (35.7, 7.95) radius 3.4635
  circle C2 centre (11.7, 7.95) radius 3.4679
  circle C3 centre (-12.3, 7.95) radius 3.4635
  circle C4 centre (-36.3, 7.95) radius 3.4635
  point P32 (0, 0)
  point P1 (0, 0)
  point P37 (0, 0)
  point P19 (34.2541, 11.0973)
  point P57 (13.1495, 11.1005)
  point P76 (-10.8533, 11.0969)
  point P98 (-34.8533, 11.0969)
  point P30 (50, -97.6631)
  point P31 (-50, -97.6631)
  point P35 (55, -115)
  point P36 (-55, -115)
  point P33 (-55, 115)
  horizontal L17
  perpendicular L17 L18
  parallel L17 L19
  parallel L18 L20
  coincident L21 P32
  coincident L22 P32
  coincident P1 P32
  horizontal L23
  perpendicular L23 L24
  parallel L23 L25
  parallel L24 L26
  coincident L27 P37
  coincident L28 P37
  coincident P32 P37
  concentric A3 C1
  coincident P19 C1
  concentric A7 C2
  coincident P57 C2
  concentric A11 C3
  coincident P76 C3
  concentric A15 C4
  coincident P98 C4
  dimension "d1" distance P30 P31 = 100
  dimension "d2" distance P35 P36 = 110
  dimension "d19" distance P33 P36 = 230
extrude "Extrude1" new body sketch "Sketch2" profile of L1 L2 L3 A1 L4 L5 L6 L7 A2 L8 L9 L10 L11 L12 A3 L13 L14 L15 L16 L17 L18 L19 L20 L23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 along normal blind 2
sketch "Sketch3" plane through (0, 0, 16.7) normal (0, 0, -1) x axis (1, 0, 0)
  line L1 (55, -115) -> (-55, -115)
  line L2 (55, 115) -> (55, -115)
  line L3 (-55, 115) -> (55, 115)
  line L4 (-55, -115) -> (-55, 115)
  circle C1 centre (-35.7, 7.95) radius 3.4635
  circle C2 centre (36.3, 7.95) radius 3.4635
  circle C3 centre (-11.7, 7.95) radius 3.4679
  circle C4 centre (12.3, 7.95) radius 3.4635
  circle C5 centre (39.33, 65.6) radius 1.55
  circle C6 centre (39.33, 37.5) radius 1.55
  circle C7 centre (-44.88, 37.5) radius 1.55
  circle C8 centre (-44.88, 65.6) radius 1.55
sketch "Sketch4" plane through (0, 0, 9.185) normal (0, 0, 1) x axis (-1, 0, 0)
  line L1 (30.1, 50.257) -> (29.1, 50.257)
  line L2 (30.1, 45.363) -> (30.1, 50.257)
  line L3 (29.1, 45.363) -> (30.1, 45.363)
  line L4 (29.1, 42.21) -> (29.1, 45.363)
  line L5 (28.703, 42.213) -> (29.1, 42.21)
  line L6 (27.953, 42.213) -> (28.703, 42.213)
  line L7 (27.953, 41.763) -> (27.953, 42.213)
  line L8 (33.253, 40.063) -> (29.653, 40.063)
  line L9 (33.253, 42.21) -> (33.253, 40.063)
  line L10 (38.147, 42.21) -> (33.253, 42.21)
  line L11 (38.147, 40.063) -> (38.147, 42.21)
  line L12 (41.747, 40.063) -> (38.147, 40.063)
  line L13 (43.447, 42.213) -> (43.447, 41.763)
  line L14 (42.697, 42.213) -> (43.447, 42.213)
  line L15 (42.3, 42.21) -> (42.697, 42.213)
  line L16 (42.3, 45.363) -> (42.3, 42.21)
  line L17 (41.3, 45.363) -> (42.3, 45.363)
  line L18 (41.3, 50.257) -> (41.3, 45.363)
  line L19 (42.3, 50.257) -> (41.3, 50.257)
  line L20 (42.3, 53.41) -> (42.3, 50.257)
  line L21 (42.697, 53.407) -> (42.3, 53.41)
  line L22 (43.447, 53.407) -> (42.697, 53.407)
  line L23 (43.447, 53.857) -> (43.447, 53.407)
  line L24 (38.147, 55.557) -> (41.747, 55.557)
  line L25 (38.147, 53.41) -> (38.147, 55.557)
  line L26 (33.253, 53.41) -> (38.147, 53.41)
  line L27 (33.253, 55.557) -> (33.253, 53.41)
  line L28 (29.653, 55.557) -> (33.253, 55.557)
  line L29 (27.953, 53.407) -> (27.953, 53.857)
  line L30 (28.703, 53.407) -> (27.953, 53.407)
  line L31 (29.1, 53.41) -> (28.703, 53.407)
  line L32 (29.1, 50.257) -> (29.1, 53.41)
  line L33 (17.29, 45.363) -> (18.29, 45.363)
  line L34 (17.29, 50.257) -> (17.29, 45.363)
  line L35 (18.29, 50.257) -> (17.29, 50.257)
  line L36 (18.29, 53.41) -> (18.29, 50.257)
  line L37 (18.687, 53.407) -> (18.29, 53.41)
  line L38 (19.437, 53.407) -> (18.687, 53.407)
  line L39 (19.437, 53.857) -> (19.437, 53.407)
  line L40 (14.137, 55.557) -> (17.737, 55.557)
  line L41 (14.137, 53.41) -> (14.137, 55.557)
  line L42 (9.243, 53.41) -> (14.137, 53.41)
  line L43 (9.243, 55.557) -> (9.243, 53.41)
  line L44 (5.643, 55.557) -> (9.243, 55.557)
  line L45 (3.943, 53.407) -> (3.943, 53.857)
  line L46 (4.693, 53.407) -> (3.943, 53.407)
  line L47 (5.09, 53.41) -> (4.693, 53.407)
  line L48 (5.09, 50.257) -> (5.09, 53.41)
  line L49 (6.09, 50.257) -> (5.09, 50.257)
  line L50 (6.09, 45.363) -> (6.09, 50.257)
  line L51 (5.09, 45.363) -> (6.09, 45.363)
  line L52 (5.09, 42.21) -> (5.09, 45.363)
  line L53 (4.693, 42.213) -> (5.09, 42.21)
  line L54 (3.943, 42.213) -> (4.693, 42.213)
  line L55 (3.943, 41.763) -> (3.943, 42.213)
  line L56 (9.243, 40.063) -> (5.643, 40.063)
  line L57 (9.243, 42.21) -> (9.243, 40.063)
  line L58 (14.137, 42.21) -> (9.243, 42.21)
  line L59 (14.137, 40.063) -> (14.137, 42.21)
  line L60 (17.737, 40.063) -> (14.137, 40.063)
  line L61 (19.437, 42.213) -> (19.437, 41.763)
  line L62 (18.687, 42.213) -> (19.437, 42.213)
  line L63 (18.29, 42.21) -> (18.687, 42.213)
  line L64 (18.29, 45.363) -> (18.29, 42.21)
  line L65 (-30.75, 45.363) -> (-29.75, 45.363)
  line L66 (-30.75, 50.257) -> (-30.75, 45.363)
  line L67 (-29.75, 50.257) -> (-30.75, 50.257)
  line L68 (-29.75, 53.41) -> (-29.75, 50.257)
  line L69 (-29.353, 53.407) -> (-29.75, 53.41)
  line L70 (-28.603, 53.407) -> (-29.353, 53.407)
  line L71 (-28.603, 53.857) -> (-28.603, 53.407)
  line L72 (-33.903, 55.557) -> (-30.303, 55.557)
  line L73 (-33.903, 53.41) -> (-33.903, 55.557)
  line L74 (-38.797, 53.41) -> (-33.903, 53.41)
  line L75 (-38.797, 55.557) -> (-38.797, 53.41)
  line L76 (-42.397, 55.557) -> (-38.797, 55.557)
  line L77 (-44.097, 53.407) -> (-44.097, 53.857)
  line L78 (-43.347, 53.407) -> (-44.097, 53.407)
  line L79 (-42.95, 53.41) -> (-43.347, 53.407)
  line L80 (-42.95, 50.257) -> (-42.95, 53.41)
  line L81 (-41.95, 50.257) -> (-42.95, 50.257)
  line L82 (-41.95, 45.363) -> (-41.95, 50.257)
  line L83 (-42.95, 45.363) -> (-41.95, 45.363)
  line L84 (-42.95, 42.21) -> (-42.95, 45.363)
  line L85 (-43.347, 42.213) -> (-42.95, 42.21)
  line L86 (-44.097, 42.213) -> (-43.347, 42.213)
  line L87 (-44.097, 41.763) -> (-44.097, 42.213)
  line L88 (-38.797, 40.063) -> (-42.397, 40.063)
  line L89 (-38.797, 42.21) -> (-38.797, 40.063)
  line L90 (-33.903, 42.21) -> (-38.797, 42.21)
  line L91 (-33.903, 40.063) -> (-33.903, 42.21)
  line L92 (-30.303, 40.063) -> (-33.903, 40.063)
  line L93 (-28.603, 42.213) -> (-28.603, 41.763)
  line L94 (-29.353, 42.213) -> (-28.603, 42.213)
  line L95 (-29.75, 42.21) -> (-29.353, 42.213)
  line L96 (-29.75, 45.363) -> (-29.75, 42.21)
  line L97 (-8.33, 51.81) -> (-16.33, 51.81)
  line L98 (-16.33, 51.81) -> (-8.33, 51.81)
  line L99 (-16.33, 51.81) -> (-16.33, 43.81)
  line L100 (-16.33, 43.81) -> (-16.33, 51.81)
  line L101 (-8.33, 43.81) -> (-8.33, 51.81)
  line L102 (-8.33, 51.81) -> (-8.33, 43.81)
  line L103 (-16.33, 43.81) -> (-8.33, 43.81)
  line L104 (-8.33, 43.81) -> (-16.33, 43.81)
  line L105 (-47.3233, 33.6231) -> (49.0612, 33.6231)
  line L106 (-47.3233, 70.4822) -> (-47.3233, 33.6231)
  line L107 (49.0612, 70.4822) -> (-47.3233, 70.4822)
  line L108 (49.0612, 33.6231) -> (49.0612, 70.4822)
  line L109 (4.59, 42.713) -> (4.59, 45.863)
  line L110 (3.443, 42.713) -> (4.59, 42.713)
  line L111 (3.443, 41.763) -> (3.443, 42.713)
  line L112 (9.743, 39.563) -> (5.643, 39.563)
  line L113 (9.743, 41.71) -> (9.743, 39.563)
  line L114 (13.637, 41.71) -> (9.743, 41.71)
  line L115 (13.637, 39.563) -> (13.637, 41.71)
  line L116 (17.737, 39.563) -> (13.637, 39.563)
  line L117 (19.937, 42.713) -> (19.937, 41.763)
  line L118 (18.79, 42.713) -> (19.937, 42.713)
  line L119 (18.79, 45.863) -> (18.79, 42.713)
  line L120 (17.79, 45.863) -> (18.79, 45.863)
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  horizontal L105
  vertical L106
  horizontal L107
  vertical L108
  dimension "d5" = 0.5
  dimension "d6" = 0.5
  dimension "d7" = 0.5
  dimension "d8" = -0.5
extrude "Extrude2" new body sketch "Sketch4" against normal blind 2
component_from_bodies "Body->Comp"
position "Position2"
sketch "Sketch5" plane through (0, 0, 18.7) normal (0, 0, 1) x axis (-1, 0, 0)
  line L1 (55, -115) -> (-55, -115)
  line L2 (55, 115) -> (55, -115)
  line L3 (-55, 115) -> (55, 115)
  line L4 (-55, -115) -> (-55, 115)
  line L5 (49.0612, 33.6231) -> (49.0612, 70.4822)
  line L6 (49.0612, 70.4822) -> (-47.3233, 70.4822)
  line L7 (-47.3233, 33.6231) -> (49.0612, 33.6231)
  line L8 (-47.3233, 70.4822) -> (-47.3233, 33.6231)
  circle C1 centre (35.7, 7.95) radius 3.4635
  circle C2 centre (-36.3, 7.95) radius 3.4635
  circle C3 centre (11.7, 7.95) radius 3.4679
  circle C4 centre (-12.3, 7.95) radius 3.4635
  circle C5 centre (44.88, 65.6) radius 1.55
  circle C6 centre (44.88, 37.5) radius 1.55
  circle C7 centre (-39.33, 65.6) radius 1.55
  circle C8 centre (-39.33, 37.5) radius 1.55
extrude "Extrude3" cut sketch "Sketch5" profile of C5 C6 C7 C8 against normal blind 4
component_insert "Component Insert4"
position "Position3"
combine "Combine1"
sketch "Sketch6" plane through (0, 0, 18.7) normal (0, 0, 1) x axis (-1, 0, 0)
  line L1 (-48.7625, -18.5942) -> (48.9191, -18.5942)
  line L2 (-48.7625, -71.4735) -> (-48.7625, -18.5942)
  line L3 (48.9191, -71.4735) -> (-48.7625, -71.4735)
  line L4 (48.9191, -18.5942) -> (48.9191, -71.4735)
offset_faces "OffsetFaces1" distance 5.919
offset_faces "OffsetFaces2" distance 6.081
fillet "Fillet1" radius 10
position "Position4"
sketch "Sketch7" plane through (0, 0, 18.7) normal (0, 0, 1) x axis (-1, 0, 0)
  line L1 (50.919, -115) -> (-51.081, -115)
  line L2 (60.919, 105) -> (60.919, -105)
  line L3 (-51.081, 115) -> (50.919, 115)
  line L4 (-61.081, -105) -> (-61.081, 105)
  line L5 (53.8484, -42.5942) -> (53.8484, -103.4735)
  line L6 (-53.7625, -105.1735) -> (-53.7625, -42.5942)
  line L7 (48.9191, -45.5942) -> (-48.7625, -45.5942)
  line L8 (48.9191, -98.4735) -> (48.9191, -45.5942)
  line L9 (-48.7625, -98.4735) -> (48.9191, -98.4735)
  line L10 (-48.7625, -45.5942) -> (-48.7625, -98.4735)
  line L11 (-53.7625, -42.5942) -> (53.8484, -42.5942)
  line L12 (-53.7625, -51.3779) -> (-53.7625, -42.5942)
  line L13 (53.8484, -51.3779) -> (-53.7625, -51.3779)
  line L14 (53.8484, -42.5942) -> (53.8484, -51.3779)
  line L15 (-53.7625, -78.1735) -> (53.8485, -78.1735)
  line L16 (-53.7625, -15.5942) -> (-53.7625, -78.1735)
  line L17 (53.8484, -15.5942) -> (-53.7625, -15.5942)
  line L18 (53.8484, -76.4735) -> (53.8484, -15.5942)
  line L19 (53.8485, -76.4735) -> (53.8484, -76.4735)
  line L20 (53.8485, -78.1735) -> (53.8485, -76.4735)
  line L21 (-53.7625, -42.5942) -> (53.8484, -42.5942)
  line L22 (53.8485, -105.1735) -> (-53.7625, -105.1735)
  line L23 (53.8485, -103.4735) -> (53.8485, -105.1735)
  line L24 (53.8484, -103.4735) -> (53.8485, -103.4735)
  arc A1 centre (-51.081, -105) radius 10 clockwise from (-51.081, -115) to (-61.081, -105)
  arc A2 centre (50.919, -105) radius 10 clockwise from (60.919, -105) to (50.919, -115)
  arc A3 centre (50.919, 105) radius 10 clockwise from (50.919, 115) to (60.919, 105)
  arc A4 centre (-51.081, 105) radius 10 clockwise from (-61.081, 105) to (-51.081, 115)
  circle C1 centre (44.88, 65.6) radius 1.55
  circle C2 centre (-39.33, 65.6) radius 1.55
  circle C3 centre (44.88, 37.5) radius 1.55
  circle C4 centre (-39.33, 37.5) radius 1.55
  circle C5 centre (11.7, 7.95) radius 3.4679
  circle C6 centre (-12.3, 7.95) radius 3.4635
  circle C7 centre (-36.3, 7.95) radius 3.4635
  circle C8 centre (35.7, 7.95) radius 3.4635
  point P23 (53.8484, -42.5942)
  point P30 (53.8484, -42.5942)
  horizontal L11
  vertical L12
  horizontal L13
  vertical L14
  coincident P23 P30
extrude "Extrude5" add sketch "Sketch7" profile of L11 L12 L13 L14 against normal blind 2
extrude "Extrude6" cut sketch "Sketch7" profile of L5 L6 L8 L9 L10 against normal blind 2
delete_face "DeleteFace1"
delete_face "DeleteFace2"
delete_face "DeleteFace3"
delete_face "DeleteFace4"
delete_face "DeleteFace5"
move "Move1"
position "Position5"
